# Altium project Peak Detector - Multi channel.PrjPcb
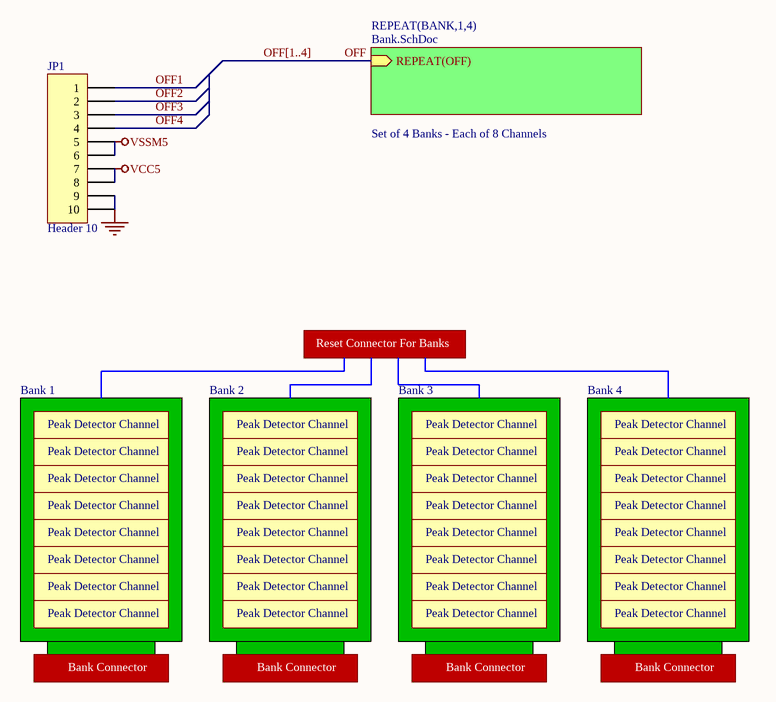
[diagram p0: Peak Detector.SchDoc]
3 sheets, 549 parts. Net scope: hierarchical (ports join the sheet entries above them; power ports are global).
Board file: Peak Detector With Banking.PcbDoc
Sheets:
  Peak Detector.SchDoc
    BANK1 = Bank.SchDoc
      PD1 = Peak Detector - channel.SchDoc
      PD2 = Peak Detector - channel.SchDoc
      PD3 = Peak Detector - channel.SchDoc
      PD4 = Peak Detector - channel.SchDoc
      PD5 = Peak Detector - channel.SchDoc
      PD6 = Peak Detector - channel.SchDoc
      PD7 = Peak Detector - channel.SchDoc
      PD8 = Peak Detector - channel.SchDoc
    BANK2 = Bank.SchDoc
      PD1 = Peak Detector - channel.SchDoc
      PD2 = Peak Detector - channel.SchDoc
      PD3 = Peak Detector - channel.SchDoc
      PD4 = Peak Detector - channel.SchDoc
      PD5 = Peak Detector - channel.SchDoc
      PD6 = Peak Detector - channel.SchDoc
      PD7 = Peak Detector - channel.SchDoc
      PD8 = Peak Detector - channel.SchDoc
    BANK3 = Bank.SchDoc
      PD1 = Peak Detector - channel.SchDoc
      PD2 = Peak Detector - channel.SchDoc
      PD3 = Peak Detector - channel.SchDoc
      PD4 = Peak Detector - channel.SchDoc
      PD5 = Peak Detector - channel.SchDoc
      PD6 = Peak Detector - channel.SchDoc
      PD7 = Peak Detector - channel.SchDoc
      PD8 = Peak Detector - channel.SchDoc
    BANK4 = Bank.SchDoc
      PD1 = Peak Detector - channel.SchDoc
      PD2 = Peak Detector - channel.SchDoc
      PD3 = Peak Detector - channel.SchDoc
      PD4 = Peak Detector - channel.SchDoc
      PD5 = Peak Detector - channel.SchDoc
      PD6 = Peak Detector - channel.SchDoc
      PD7 = Peak Detector - channel.SchDoc
      PD8 = Peak Detector - channel.SchDoc

## Sheet Peak Detector.SchDoc
size A; Organization: Altium Limited; Address1: L3, 12a Rodborough Rd; Address2: Frenchs Forest; Address3: NSW; Address4: Australia 2086; DocumentNumber: 2; SheetNumber: 2; SheetTotal: 3

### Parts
JP1  Header 10  [HDR1X10]

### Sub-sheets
REPEAT(BANK,1,4) = Bank.SchDoc: REPEAT(OFF) (in)  | Description: Set of 4 Banks - Each of 8 Channels

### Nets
GND: JP1.9 JP1.10
VCC5: JP1.7 JP1.8
VSSM5: JP1.5 JP1.6
OFF1: JP1.1
OFF2: JP1.2
OFF3: JP1.3
OFF4: JP1.4

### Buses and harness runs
bus OFF[1..4]

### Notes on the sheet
- Reset Connector For Banks
- Bank 1
- Peak Detector Channel
- Bank 2
- Bank 3
- Bank 4
- Bank Connector

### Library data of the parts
JP1 = Header 10: Header, 10-Pin; Manufacturer: Generic Components; Class: Connector

## Sheet Bank.SchDoc
size A; Organization: Altium Limited; Address1: L3, 12a Rodborough Rd; Address2: Frenchs Forest; Address3: NSW; Address4: Australia 2086; DocumentNumber: 3; SheetNumber: 3; SheetTotal: 3
Used 4 times, as channels BANK1, BANK2, BANK3, BANK4. Parts and nets are listed once, with the designators drawn on the sheet.
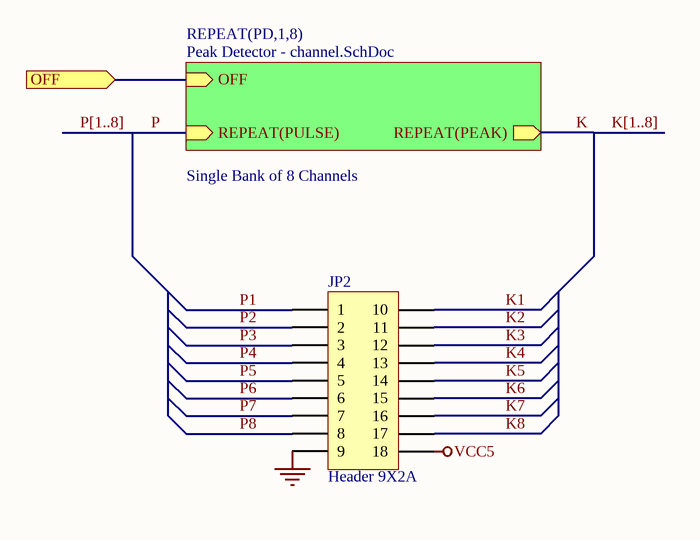
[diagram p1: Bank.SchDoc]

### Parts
JP2  Header 9X2A  [FFC/SM0.5-2H18A]

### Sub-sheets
REPEAT(PD,1,8) = Peak Detector - channel.SchDoc: REPEAT(PULSE) (in), REPEAT(PEAK) (out), OFF  | Description: Single Bank of 8 Channels

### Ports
OFF

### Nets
GND: JP2.9
VCC5: JP2.18
K1: JP2.10
K2: JP2.11
K3: JP2.12
K4: JP2.13
K5: JP2.14
K6: JP2.15
K7: JP2.16
K8: JP2.17
OFF: port OFF, sheet REPEAT(PD,1,8)/OFF
P1: JP2.1
P2: JP2.2
P3: JP2.3
P4: JP2.4
P5: JP2.5
P6: JP2.6
P7: JP2.7
P8: JP2.8

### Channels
BANK1: designators end in _BANK1; ports OFF=OFF1
BANK2: designators end in _BANK2; ports OFF=OFF2
BANK3: designators end in _BANK3; ports OFF=OFF3
BANK4: designators end in _BANK4; ports OFF=OFF4

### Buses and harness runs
bus K[1..8]
bus P[1..8]

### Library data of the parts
JP2 = Header 9X2A: Header, 9-Pin, Dual row; Manufacturer: Generic Components; Class: Connector

## Sheet Peak Detector - channel.SchDoc
size A; Organization: Altium Limited; Address1: L3, 12a Rodborough Rd; Address2: Frenchs Forest; Address3: NSW; Address4: Australia 2086; DocumentNumber: 1; SheetNumber: 1; SheetTotal: 3
Used 32 times, as channels BANK1/PD1, BANK1/PD2, BANK1/PD3, BANK1/PD4, BANK1/PD5, BANK1/PD6, BANK1/PD7, BANK1/PD8, BANK2/PD1, BANK2/PD2, BANK2/PD3, BANK2/PD4, BANK2/PD5, BANK2/PD6, BANK2/PD7, BANK2/PD8, BANK3/PD1, BANK3/PD2, BANK3/PD3, BANK3/PD4, BANK3/PD5, BANK3/PD6, BANK3/PD7, BANK3/PD8, BANK4/PD1, BANK4/PD2, BANK4/PD3, BANK4/PD4, BANK4/PD5, BANK4/PD6, BANK4/PD7, BANK4/PD8. Parts and nets are listed once, with the designators drawn on the sheet.
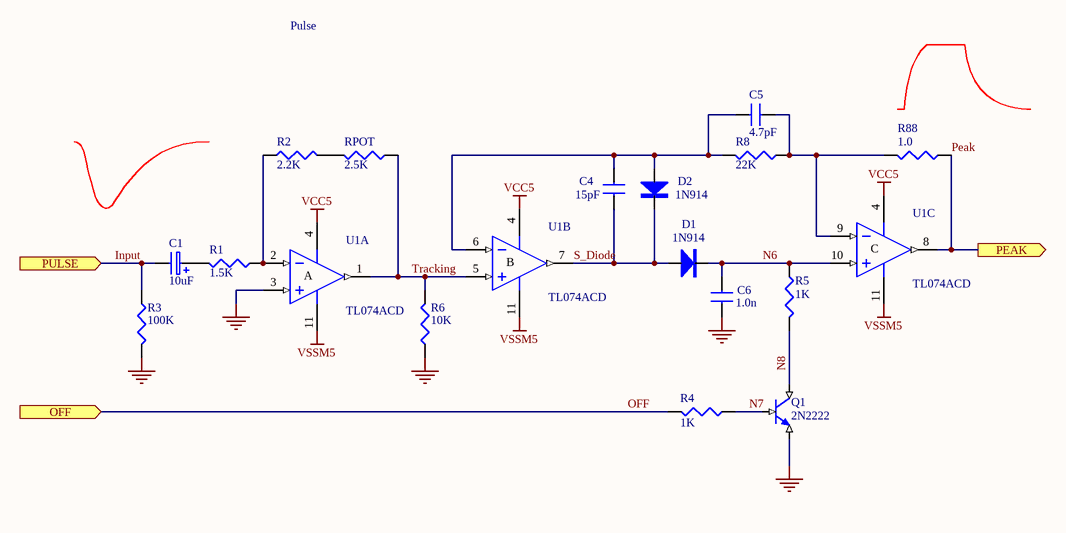
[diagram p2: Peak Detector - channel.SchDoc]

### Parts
C1  10uF  [1206]
C4  15pF  [0805]
C5  4.7pF  [0805]
C6  1.0n  [0805]
D1  1N914  [3216]
D2  1N914  [3216]
Q1  2N2222  [SO-G3/D4.1]
R1  1.5K  [0603]
R2  2.2K  [0603]
R3  100K  [0603]
R4  value 1K  [0603]  (hidden comment: 10K)
R5  1K  [0603]
R6  10K  [0603]
R8  22K  [0603]
R88  1.0  [0603]
RPOT  2.5K  [0603]
U1  TL074ACD  [SO-G14/G3]  (parts A,B,C of 4)

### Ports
OFF (in), PEAK (out), PULSE (in)

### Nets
GND: C6.1 Q1.3(E) R3.1(TOP) R6.2(BOT) U1.3(IN+)
VCC5: U1.4(V+)
VSSM5: U1.11(V-)
Input: C1.2 R3.2(BOT) ; port PULSE
N6: C6.2 D1.2(K) R5.1(TOP) U1.10(IN+)
N7: Q1.2(B) R4.2(BOT)
N8: Q1.1(C) R5.2(BOT)
OFF: R4.1(TOP) ; port OFF
Peak: R88.2(BOT) U1.8(OUT) ; port PEAK
S_Diode: C4.2 D1.1(A) D2.2(K) U1.7(OUT)
Tracking: R6.1(TOP) RPOT.2(BOT) U1.1(OUT) U1.5(IN+)
NetC1_1: C1.1 R1.1(TOP)
NetC4_1: C4.1 C5.1 D2.1(A) R8.1(TOP) U1.6(IN-)
NetC5_2: C5.2 R8.2(BOT) R88.1(TOP) U1.9(IN-)
NetR1_2: R1.2(BOT) R2.2(BOT) U1.2(IN-)
NetR2_1: R2.1(TOP) RPOT.1(TOP)

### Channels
BANK1/PD1: designators end in _PD1; ports OFF=OFF1 PEAK=K1_BANK1 PULSE=P1_BANK1
BANK1/PD2: designators end in _PD2; ports OFF=OFF1 PEAK=K2_BANK1 PULSE=P2_BANK1
BANK1/PD3: designators end in _PD3; ports OFF=OFF1 PEAK=K3_BANK1 PULSE=P3_BANK1
BANK1/PD4: designators end in _PD4; ports OFF=OFF1 PEAK=K4_BANK1 PULSE=P4_BANK1
BANK1/PD5: designators end in _PD5; ports OFF=OFF1 PEAK=K5_BANK1 PULSE=P5_BANK1
BANK1/PD6: designators end in _PD6; ports OFF=OFF1 PEAK=K6_BANK1 PULSE=P6_BANK1
BANK1/PD7: designators end in _PD7; ports OFF=OFF1 PEAK=K7_BANK1 PULSE=P7_BANK1
BANK1/PD8: designators end in _PD8; ports OFF=OFF1 PEAK=K8_BANK1 PULSE=P8_BANK1
BANK2/PD1: designators end in _PD9; ports OFF=OFF2 PEAK=K1_BANK2 PULSE=P1_BANK2
BANK2/PD2: designators end in _PD10; ports OFF=OFF2 PEAK=K2_BANK2 PULSE=P2_BANK2
BANK2/PD3: designators end in _PD11; ports OFF=OFF2 PEAK=K3_BANK2 PULSE=P3_BANK2
BANK2/PD4: designators end in _PD12; ports OFF=OFF2 PEAK=K4_BANK2 PULSE=P4_BANK2
BANK2/PD5: designators end in _PD13; ports OFF=OFF2 PEAK=K5_BANK2 PULSE=P5_BANK2
BANK2/PD6: designators end in _PD14; ports OFF=OFF2 PEAK=K6_BANK2 PULSE=P6_BANK2
BANK2/PD7: designators end in _PD15; ports OFF=OFF2 PEAK=K7_BANK2 PULSE=P7_BANK2
BANK2/PD8: designators end in _PD16; ports OFF=OFF2 PEAK=K8_BANK2 PULSE=P8_BANK2
BANK3/PD1: designators end in _PD17; ports OFF=OFF3 PEAK=K1_BANK3 PULSE=P1_BANK3
BANK3/PD2: designators end in _PD18; ports OFF=OFF3 PEAK=K2_BANK3 PULSE=P2_BANK3
BANK3/PD3: designators end in _PD19; ports OFF=OFF3 PEAK=K3_BANK3 PULSE=P3_BANK3
BANK3/PD4: designators end in _PD20; ports OFF=OFF3 PEAK=K4_BANK3 PULSE=P4_BANK3
BANK3/PD5: designators end in _PD21; ports OFF=OFF3 PEAK=K5_BANK3 PULSE=P5_BANK3
BANK3/PD6: designators end in _PD22; ports OFF=OFF3 PEAK=K6_BANK3 PULSE=P6_BANK3
BANK3/PD7: designators end in _PD23; ports OFF=OFF3 PEAK=K7_BANK3 PULSE=P7_BANK3
BANK3/PD8: designators end in _PD24; ports OFF=OFF3 PEAK=K8_BANK3 PULSE=P8_BANK3
BANK4/PD1: designators end in _PD25; ports OFF=OFF4 PEAK=K1_BANK4 PULSE=P1_BANK4
BANK4/PD2: designators end in _PD26; ports OFF=OFF4 PEAK=K2_BANK4 PULSE=P2_BANK4
BANK4/PD3: designators end in _PD27; ports OFF=OFF4 PEAK=K3_BANK4 PULSE=P3_BANK4
BANK4/PD4: designators end in _PD28; ports OFF=OFF4 PEAK=K4_BANK4 PULSE=P4_BANK4
BANK4/PD5: designators end in _PD29; ports OFF=OFF4 PEAK=K5_BANK4 PULSE=P5_BANK4
BANK4/PD6: designators end in _PD30; ports OFF=OFF4 PEAK=K6_BANK4 PULSE=P6_BANK4
BANK4/PD7: designators end in _PD31; ports OFF=OFF4 PEAK=K7_BANK4 PULSE=P7_BANK4
BANK4/PD8: designators end in _PD32; ports OFF=OFF4 PEAK=K8_BANK4 PULSE=P8_BANK4

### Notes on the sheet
- Pulse

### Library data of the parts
C1 = CAP3: Capacitor
C4-C6 = CAP: Capacitor
D1 D2 = 1N914: Diode
Q1 = 2N2222: NPN BJT
R1-R6 R8 R88 RPOT = RES: Resistor
U1 = TL074ACD: Low-Noise J-FET Quad Operational Amplifier; Text Field7: Published 24-Aug-2001

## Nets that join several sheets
GND: Peak Detector (JP1.9 JP1.10), BANK1 (JP2_BANK1.9), BANK1/PD1 (5 pins), BANK1/PD2 (5 pins), BANK1/PD3 (5 pins), BANK1/PD4 (5 pins), BANK1/PD5 (5 pins), BANK1/PD6 (5 pins), BANK1/PD7 (5 pins), BANK1/PD8 (5 pins), BANK2 (JP2_BANK2.9), BANK2/PD1 (5 pins), BANK2/PD2 (5 pins), BANK2/PD3 (5 pins), BANK2/PD4 (5 pins), BANK2/PD5 (5 pins), BANK2/PD6 (5 pins), BANK2/PD7 (5 pins), BANK2/PD8 (5 pins), BANK3 (JP2_BANK3.9), BANK3/PD1 (5 pins), BANK3/PD2 (5 pins), BANK3/PD3 (5 pins), BANK3/PD4 (5 pins), BANK3/PD5 (5 pins), BANK3/PD6 (5 pins), BANK3/PD7 (5 pins), BANK3/PD8 (5 pins), BANK4 (JP2_BANK4.9), BANK4/PD1 (5 pins), BANK4/PD2 (5 pins), BANK4/PD3 (5 pins), BANK4/PD4 (5 pins), BANK4/PD5 (5 pins), BANK4/PD6 (5 pins), BANK4/PD7 (5 pins), BANK4/PD8 (5 pins)
VCC5: Peak Detector (JP1.7 JP1.8), BANK1 (JP2_BANK1.18), BANK1/PD1 (U1_PD1.4), BANK1/PD2 (U1_PD2.4), BANK1/PD3 (U1_PD3.4), BANK1/PD4 (U1_PD4.4), BANK1/PD5 (U1_PD5.4), BANK1/PD6 (U1_PD6.4), BANK1/PD7 (U1_PD7.4), BANK1/PD8 (U1_PD8.4), BANK2 (JP2_BANK2.18), BANK2/PD1 (U1_PD9.4), BANK2/PD2 (U1_PD10.4), BANK2/PD3 (U1_PD11.4), BANK2/PD4 (U1_PD12.4), BANK2/PD5 (U1_PD13.4), BANK2/PD6 (U1_PD14.4), BANK2/PD7 (U1_PD15.4), BANK2/PD8 (U1_PD16.4), BANK3 (JP2_BANK3.18), BANK3/PD1 (U1_PD17.4), BANK3/PD2 (U1_PD18.4), BANK3/PD3 (U1_PD19.4), BANK3/PD4 (U1_PD20.4), BANK3/PD5 (U1_PD21.4), BANK3/PD6 (U1_PD22.4), BANK3/PD7 (U1_PD23.4), BANK3/PD8 (U1_PD24.4), BANK4 (JP2_BANK4.18), BANK4/PD1 (U1_PD25.4), BANK4/PD2 (U1_PD26.4), BANK4/PD3 (U1_PD27.4), BANK4/PD4 (U1_PD28.4), BANK4/PD5 (U1_PD29.4), BANK4/PD6 (U1_PD30.4), BANK4/PD7 (U1_PD31.4), BANK4/PD8 (U1_PD32.4)
VSSM5: Peak Detector (JP1.5 JP1.6), BANK1/PD1 (U1_PD1.11), BANK1/PD2 (U1_PD2.11), BANK1/PD3 (U1_PD3.11), BANK1/PD4 (U1_PD4.11), BANK1/PD5 (U1_PD5.11), BANK1/PD6 (U1_PD6.11), BANK1/PD7 (U1_PD7.11), BANK1/PD8 (U1_PD8.11), BANK2/PD1 (U1_PD9.11), BANK2/PD2 (U1_PD10.11), BANK2/PD3 (U1_PD11.11), BANK2/PD4 (U1_PD12.11), BANK2/PD5 (U1_PD13.11), BANK2/PD6 (U1_PD14.11), BANK2/PD7 (U1_PD15.11), BANK2/PD8 (U1_PD16.11), BANK3/PD1 (U1_PD17.11), BANK3/PD2 (U1_PD18.11), BANK3/PD3 (U1_PD19.11), BANK3/PD4 (U1_PD20.11), BANK3/PD5 (U1_PD21.11), BANK3/PD6 (U1_PD22.11), BANK3/PD7 (U1_PD23.11), BANK3/PD8 (U1_PD24.11), BANK4/PD1 (U1_PD25.11), BANK4/PD2 (U1_PD26.11), BANK4/PD3 (U1_PD27.11), BANK4/PD4 (U1_PD28.11), BANK4/PD5 (U1_PD29.11), BANK4/PD6 (U1_PD30.11), BANK4/PD7 (U1_PD31.11), BANK4/PD8 (U1_PD32.11)
K1_BANK1: BANK1 (JP2_BANK1.10), BANK1/PD1 (R88_PD1.2 U1_PD1.8)
K1_BANK2: BANK2 (JP2_BANK2.10), BANK2/PD1 (R88_PD9.2 U1_PD9.8)
K1_BANK3: BANK3 (JP2_BANK3.10), BANK3/PD1 (R88_PD17.2 U1_PD17.8)
K1_BANK4: BANK4 (JP2_BANK4.10), BANK4/PD1 (R88_PD25.2 U1_PD25.8)
K2_BANK1: BANK1 (JP2_BANK1.11), BANK1/PD2 (R88_PD2.2 U1_PD2.8)
K2_BANK2: BANK2 (JP2_BANK2.11), BANK2/PD2 (R88_PD10.2 U1_PD10.8)
K2_BANK3: BANK3 (JP2_BANK3.11), BANK3/PD2 (R88_PD18.2 U1_PD18.8)
K2_BANK4: BANK4 (JP2_BANK4.11), BANK4/PD2 (R88_PD26.2 U1_PD26.8)
K3_BANK1: BANK1 (JP2_BANK1.12), BANK1/PD3 (R88_PD3.2 U1_PD3.8)
K3_BANK2: BANK2 (JP2_BANK2.12), BANK2/PD3 (R88_PD11.2 U1_PD11.8)
K3_BANK3: BANK3 (JP2_BANK3.12), BANK3/PD3 (R88_PD19.2 U1_PD19.8)
K3_BANK4: BANK4 (JP2_BANK4.12), BANK4/PD3 (R88_PD27.2 U1_PD27.8)
K4_BANK1: BANK1 (JP2_BANK1.13), BANK1/PD4 (R88_PD4.2 U1_PD4.8)
K4_BANK2: BANK2 (JP2_BANK2.13), BANK2/PD4 (R88_PD12.2 U1_PD12.8)
K4_BANK3: BANK3 (JP2_BANK3.13), BANK3/PD4 (R88_PD20.2 U1_PD20.8)
K4_BANK4: BANK4 (JP2_BANK4.13), BANK4/PD4 (R88_PD28.2 U1_PD28.8)
K5_BANK1: BANK1 (JP2_BANK1.14), BANK1/PD5 (R88_PD5.2 U1_PD5.8)
K5_BANK2: BANK2 (JP2_BANK2.14), BANK2/PD5 (R88_PD13.2 U1_PD13.8)
K5_BANK3: BANK3 (JP2_BANK3.14), BANK3/PD5 (R88_PD21.2 U1_PD21.8)
K5_BANK4: BANK4 (JP2_BANK4.14), BANK4/PD5 (R88_PD29.2 U1_PD29.8)
K6_BANK1: BANK1 (JP2_BANK1.15), BANK1/PD6 (R88_PD6.2 U1_PD6.8)
K6_BANK2: BANK2 (JP2_BANK2.15), BANK2/PD6 (R88_PD14.2 U1_PD14.8)
K6_BANK3: BANK3 (JP2_BANK3.15), BANK3/PD6 (R88_PD22.2 U1_PD22.8)
K6_BANK4: BANK4 (JP2_BANK4.15), BANK4/PD6 (R88_PD30.2 U1_PD30.8)
K7_BANK1: BANK1 (JP2_BANK1.16), BANK1/PD7 (R88_PD7.2 U1_PD7.8)
K7_BANK2: BANK2 (JP2_BANK2.16), BANK2/PD7 (R88_PD15.2 U1_PD15.8)
K7_BANK3: BANK3 (JP2_BANK3.16), BANK3/PD7 (R88_PD23.2 U1_PD23.8)
K7_BANK4: BANK4 (JP2_BANK4.16), BANK4/PD7 (R88_PD31.2 U1_PD31.8)
K8_BANK1: BANK1 (JP2_BANK1.17), BANK1/PD8 (R88_PD8.2 U1_PD8.8)
K8_BANK2: BANK2 (JP2_BANK2.17), BANK2/PD8 (R88_PD16.2 U1_PD16.8)
K8_BANK3: BANK3 (JP2_BANK3.17), BANK3/PD8 (R88_PD24.2 U1_PD24.8)
K8_BANK4: BANK4 (JP2_BANK4.17), BANK4/PD8 (R88_PD32.2 U1_PD32.8)
OFF1: Peak Detector (JP1.1), BANK1/PD1 (R4_PD1.1), BANK1/PD2 (R4_PD2.1), BANK1/PD3 (R4_PD3.1), BANK1/PD4 (R4_PD4.1), BANK1/PD5 (R4_PD5.1), BANK1/PD6 (R4_PD6.1), BANK1/PD7 (R4_PD7.1), BANK1/PD8 (R4_PD8.1)
OFF2: Peak Detector (JP1.2), BANK2/PD1 (R4_PD9.1), BANK2/PD2 (R4_PD10.1), BANK2/PD3 (R4_PD11.1), BANK2/PD4 (R4_PD12.1), BANK2/PD5 (R4_PD13.1), BANK2/PD6 (R4_PD14.1), BANK2/PD7 (R4_PD15.1), BANK2/PD8 (R4_PD16.1)
OFF3: Peak Detector (JP1.3), BANK3/PD1 (R4_PD17.1), BANK3/PD2 (R4_PD18.1), BANK3/PD3 (R4_PD19.1), BANK3/PD4 (R4_PD20.1), BANK3/PD5 (R4_PD21.1), BANK3/PD6 (R4_PD22.1), BANK3/PD7 (R4_PD23.1), BANK3/PD8 (R4_PD24.1)
OFF4: Peak Detector (JP1.4), BANK4/PD1 (R4_PD25.1), BANK4/PD2 (R4_PD26.1), BANK4/PD3 (R4_PD27.1), BANK4/PD4 (R4_PD28.1), BANK4/PD5 (R4_PD29.1), BANK4/PD6 (R4_PD30.1), BANK4/PD7 (R4_PD31.1), BANK4/PD8 (R4_PD32.1)
P1_BANK1: BANK1 (JP2_BANK1.1), BANK1/PD1 (C1_PD1.2 R3_PD1.2)
P1_BANK2: BANK2 (JP2_BANK2.1), BANK2/PD1 (C1_PD9.2 R3_PD9.2)
P1_BANK3: BANK3 (JP2_BANK3.1), BANK3/PD1 (C1_PD17.2 R3_PD17.2)
P1_BANK4: BANK4 (JP2_BANK4.1), BANK4/PD1 (C1_PD25.2 R3_PD25.2)
P2_BANK1: BANK1 (JP2_BANK1.2), BANK1/PD2 (C1_PD2.2 R3_PD2.2)
P2_BANK2: BANK2 (JP2_BANK2.2), BANK2/PD2 (C1_PD10.2 R3_PD10.2)
P2_BANK3: BANK3 (JP2_BANK3.2), BANK3/PD2 (C1_PD18.2 R3_PD18.2)
P2_BANK4: BANK4 (JP2_BANK4.2), BANK4/PD2 (C1_PD26.2 R3_PD26.2)
P3_BANK1: BANK1 (JP2_BANK1.3), BANK1/PD3 (C1_PD3.2 R3_PD3.2)
P3_BANK2: BANK2 (JP2_BANK2.3), BANK2/PD3 (C1_PD11.2 R3_PD11.2)
P3_BANK3: BANK3 (JP2_BANK3.3), BANK3/PD3 (C1_PD19.2 R3_PD19.2)
P3_BANK4: BANK4 (JP2_BANK4.3), BANK4/PD3 (C1_PD27.2 R3_PD27.2)
P4_BANK1: BANK1 (JP2_BANK1.4), BANK1/PD4 (C1_PD4.2 R3_PD4.2)
P4_BANK2: BANK2 (JP2_BANK2.4), BANK2/PD4 (C1_PD12.2 R3_PD12.2)
P4_BANK3: BANK3 (JP2_BANK3.4), BANK3/PD4 (C1_PD20.2 R3_PD20.2)
P4_BANK4: BANK4 (JP2_BANK4.4), BANK4/PD4 (C1_PD28.2 R3_PD28.2)
P5_BANK1: BANK1 (JP2_BANK1.5), BANK1/PD5 (C1_PD5.2 R3_PD5.2)
P5_BANK2: BANK2 (JP2_BANK2.5), BANK2/PD5 (C1_PD13.2 R3_PD13.2)
P5_BANK3: BANK3 (JP2_BANK3.5), BANK3/PD5 (C1_PD21.2 R3_PD21.2)
P5_BANK4: BANK4 (JP2_BANK4.5), BANK4/PD5 (C1_PD29.2 R3_PD29.2)
P6_BANK1: BANK1 (JP2_BANK1.6), BANK1/PD6 (C1_PD6.2 R3_PD6.2)
P6_BANK2: BANK2 (JP2_BANK2.6), BANK2/PD6 (C1_PD14.2 R3_PD14.2)
P6_BANK3: BANK3 (JP2_BANK3.6), BANK3/PD6 (C1_PD22.2 R3_PD22.2)
P6_BANK4: BANK4 (JP2_BANK4.6), BANK4/PD6 (C1_PD30.2 R3_PD30.2)
P7_BANK1: BANK1 (JP2_BANK1.7), BANK1/PD7 (C1_PD7.2 R3_PD7.2)
P7_BANK2: BANK2 (JP2_BANK2.7), BANK2/PD7 (C1_PD15.2 R3_PD15.2)
P7_BANK3: BANK3 (JP2_BANK3.7), BANK3/PD7 (C1_PD23.2 R3_PD23.2)
P7_BANK4: BANK4 (JP2_BANK4.7), BANK4/PD7 (C1_PD31.2 R3_PD31.2)
P8_BANK1: BANK1 (JP2_BANK1.8), BANK1/PD8 (C1_PD8.2 R3_PD8.2)
P8_BANK2: BANK2 (JP2_BANK2.8), BANK2/PD8 (C1_PD16.2 R3_PD16.2)
P8_BANK3: BANK3 (JP2_BANK3.8), BANK3/PD8 (C1_PD24.2 R3_PD24.2)
P8_BANK4: BANK4 (JP2_BANK4.8), BANK4/PD8 (C1_PD32.2 R3_PD32.2)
